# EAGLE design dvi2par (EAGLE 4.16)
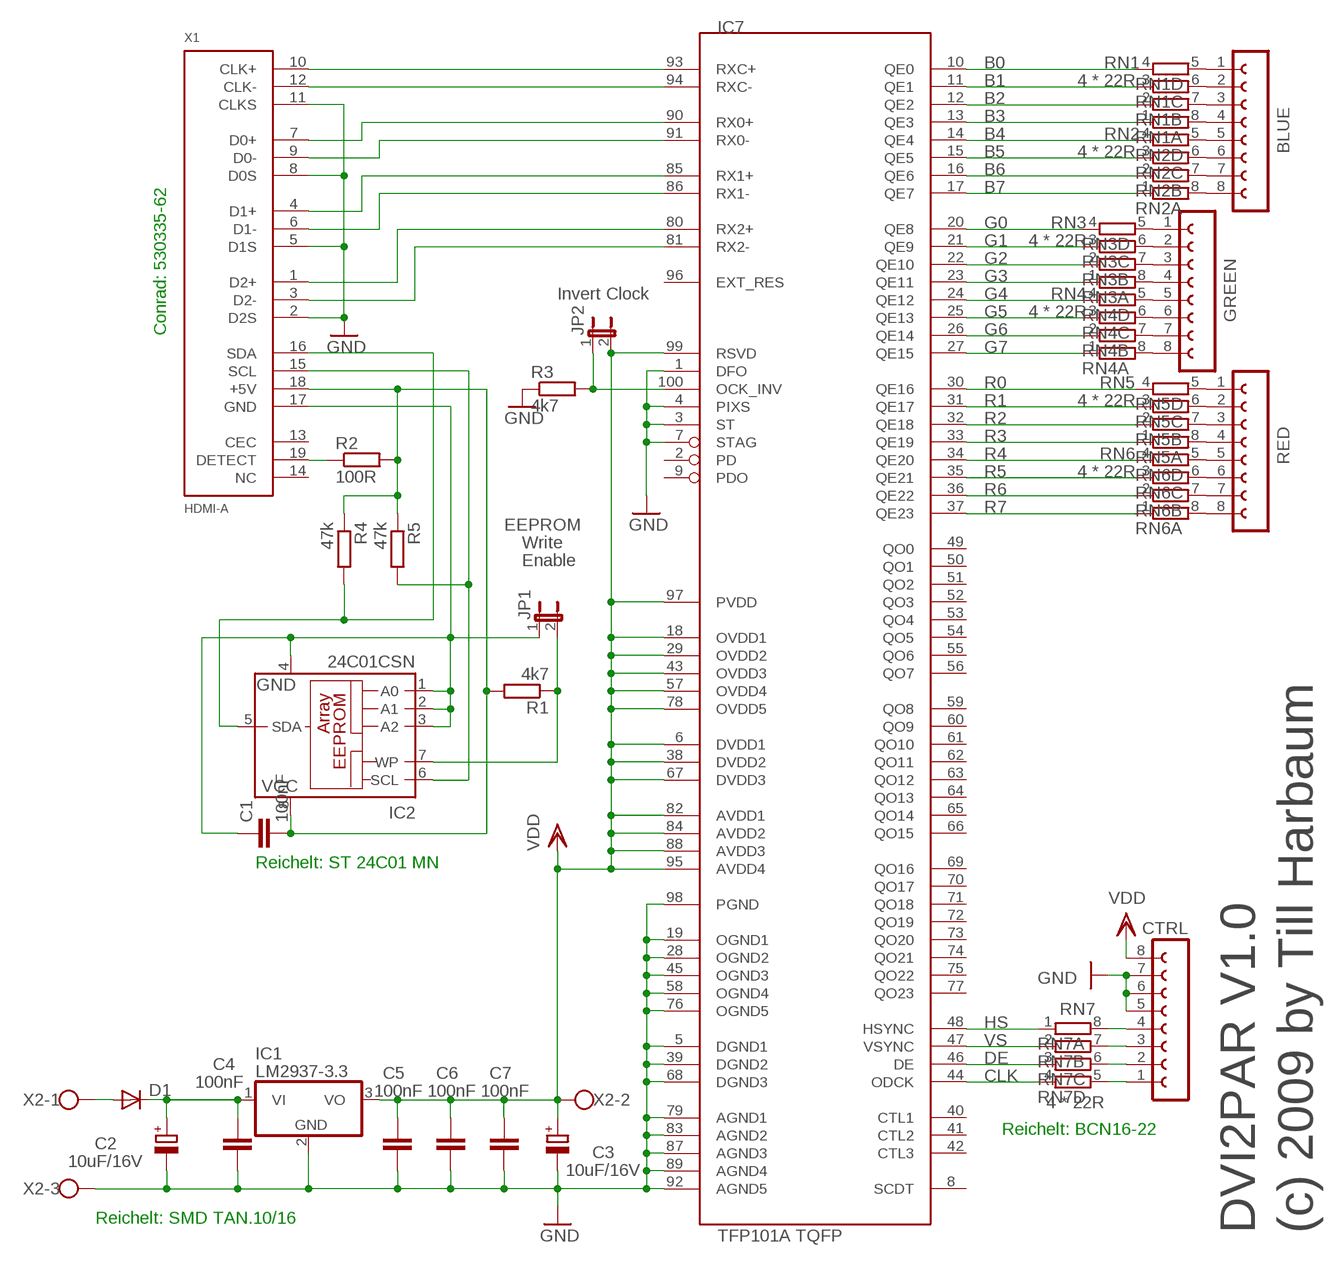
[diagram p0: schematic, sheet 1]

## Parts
BLUE  FE08-1  [FE08]
C1  100nF  C-EUC0805K  [C0805K]
C2  10uF/16V  CPOL-EUCT6032  [CT6032]
C3  10uF/16V  CPOL-EUCT6032  [CT6032]
C4  100nF  C-EUC0805K  [C0805K]
C5  100nF  C-EUC0805K  [C0805K]
C6  100nF  C-EUC0805K  [C0805K]
C7  100nF  C-EUC0805K  [C0805K]
CTRL  FE08-1  [FE08]
D1  DIODE-MELF-MLL41  [MELF-MLL41]
GREEN  FE08-1  [FE08]
IC1  LM2937-3.3  7805T  [TO220H]
IC2  24C01CSN  [SO-08]
IC7  TFP101A TQFP  TFP101ATQFP  [TQ100]
JP1  JP1E  [JP1]
JP2  JP1E  [JP1]
R1  4k7  R-EU_M0805  [M0805]
R2  100R  R-EU_R0805  [R0805]
R3  4k7  R-EU_R0805  [R0805]
R4  47k  R-EU_M0805  [M0805]
R5  47k  R-EU_M0805  [M0805]
RED  FE08-1  [FE08]
RN1  4R-N0603-ARV  [0603-ARV]
RN2  4R-N0603-ARV  [0603-ARV]
RN3  4R-N0603-ARV  [0603-ARV]
RN4  4R-N0603-ARV  [0603-ARV]
RN5  4R-N0603-ARV  [0603-ARV]
RN6  4R-N0603-ARV  [0603-ARV]
RN7  4R-N0603-ARV  [0603-ARV]
X1  HDMI-A  [HDMI-A-PRINT]
X2  W237-03P  [W237-133]

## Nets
B0: IC7.10(QE0) RN1.4
B1: IC7.11(QE1) RN1.3
B2: IC7.12(QE2) RN1.2
B3: IC7.13(QE3) RN1.1
B4: IC7.14(QE4) RN2.4
B5: IC7.15(QE5) RN2.3
B6: IC7.16(QE6) RN2.2
B7: IC7.17(QE7) RN2.1
CLK: IC7.44(ODCK) RN7.4
DDCDATA: IC2.5(SDA) R4.2 X1.16(SDA)
DDCGND: C1.1 IC2.1(A0) IC2.2(A1) IC2.3(A2) IC2.4(GND) JP1.1 X1.17(GND)
DDCVCC: C1.2 IC2.8(VCC) R1.2 R2.2 R4.1 R5.1 X1.18(+5V)
DE: IC7.46(DE) RN7.3
G0: IC7.20(QE8) RN3.4
G1: IC7.21(QE9) RN3.3
G2: IC7.22(QE10) RN3.2
G3: IC7.23(QE11) RN3.1
G4: IC7.24(QE12) RN4.4
G5: IC7.25(QE13) RN4.3
G6: IC7.26(QE14) RN4.2
G7: IC7.27(QE15) RN4.1
GND: C2.- C3.- C4.1 C5.1 C6.1 C7.1 CTRL.5 CTRL.6 CTRL.7 IC1.2(GND) IC7.1(DFO) IC7.3(ST) IC7.4(PIXS) IC7.5(DGND1) IC7.7(STAG) IC7.19(OGND1) IC7.28(OGND2) IC7.39(DGND2) IC7.45(OGND3) IC7.58(OGND4) IC7.68(DGND3) IC7.76(OGND5) IC7.79(AGND1) IC7.83(AGND2) IC7.87(AGND3) IC7.89(AGND4) IC7.92(AGND5) IC7.98(PGND) R3.1 X1.2(D2S) X1.5(D1S) X1.8(D0S) X1.11(CLKS) X2.3
HS: IC7.48(HSYNC) RN7.1
N$2: IC2.7(WP) JP1.2 R1.1
N$3: R2.1 X1.19(DETECT)
N$4: BLUE.4 RN1.8
N$6: BLUE.3 RN1.7
N$8: BLUE.2 RN1.6
N$9: BLUE.1 RN1.5
N$10: BLUE.8 RN2.8
N$11: BLUE.7 RN2.7
N$12: BLUE.6 RN2.6
N$13: BLUE.5 RN2.5
N$14: GREEN.4 RN3.8
N$15: GREEN.3 RN3.7
N$16: GREEN.2 RN3.6
N$17: GREEN.1 RN3.5
N$18: GREEN.8 RN4.8
N$19: GREEN.7 RN4.7
N$20: GREEN.6 RN4.6
N$21: GREEN.5 RN4.5
N$22: RED.4 RN5.8
N$23: RED.3 RN5.7
N$24: RED.2 RN5.6
N$25: RED.1 RN5.5
N$26: RED.8 RN6.8
N$27: RED.7 RN6.7
N$28: RED.6 RN6.6
N$29: RED.5 RN6.5
N$30: CTRL.1 RN7.5
N$31: CTRL.2 RN7.6
N$32: CTRL.3 RN7.7
N$33: CTRL.4 RN7.8
N$34: IC2.6(SCL) R5.2 X1.15(SCL)
N$35: IC7.100(OCK_INV) JP2.1 R3.2
N$36: D1.A X2.1
PWR_IN: C2.+ C4.2 D1.C IC1.1(VI)
R0: IC7.30(QE16) RN5.4
R1: IC7.31(QE17) RN5.3
R2: IC7.32(QE18) RN5.2
R3: IC7.33(QE19) RN5.1
R4: IC7.34(QE20) RN6.4
R5: IC7.35(QE21) RN6.3
R6: IC7.36(QE22) RN6.2
R7: IC7.37(QE23) RN6.1
RX0+: IC7.90(RX0+) X1.7(D0+)
RX0-: IC7.91(RX0-) X1.9(D0-)
RX1+: IC7.85(RX1+) X1.4(D1+)
RX1-: IC7.86(RX1-) X1.6(D1-)
RX2+: IC7.80(RX2+) X1.1(D2+)
RX2-: IC7.81(RX2-) X1.3(D2-)
RXC+: IC7.93(RXC+) X1.10(CLK+)
RXC-: IC7.94(RXC-) X1.12(CLK-)
VDD: C3.+ C5.2 C6.2 C7.2 CTRL.8 IC1.3(VO) IC7.6(DVDD1) IC7.18(OVDD1) IC7.29(OVDD2) IC7.38(DVDD2) IC7.43(OVDD3) IC7.57(OVDD4) IC7.67(DVDD3) IC7.78(OVDD5) IC7.82(AVDD1) IC7.84(AVDD2) IC7.88(AVDD3) IC7.95(AVDD4) IC7.97(PVDD) IC7.99(RSVD) JP2.2 X2.2
VS: IC7.47(VSYNC) RN7.2
Unconnected: IC7.2(PD) IC7.8(SCDT) IC7.9(PDO) IC7.40(CTL1) IC7.41(CTL2) IC7.42(CTL3) IC7.49(QO0) IC7.50(QO1) IC7.51(QO2) IC7.52(QO3) IC7.53(QO4) IC7.54(QO5) IC7.55(QO6) IC7.56(QO7) IC7.59(QO8) IC7.60(QO9) IC7.61(QO10) IC7.62(QO11) IC7.63(QO12) IC7.64(QO13) IC7.65(QO14) IC7.66(QO15) IC7.69(QO16) IC7.70(QO17) IC7.71(QO18) IC7.72(QO19) IC7.73(QO20) IC7.74(QO21) IC7.75(QO22) IC7.77(QO23) IC7.96(EXT_RES) X1.13(CEC) X1.14(NC)

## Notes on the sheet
- RN1
- 4 * 22R
- RN2
- 4 * 22R
- RN3
- 4 * 22R
- Invert Clock | RN4
- 4 * 22R
- Conrad: 530335-62
- RN5
- 4 * 22R
- RN6
- 4 * 22R
- EEPROM
- Write
- Enable
- Reichelt: ST 24C01 MN
- RN7
- 4 * 22R
- Reichelt: BCN16-22
- Reichelt: SMD TAN.10/16
- DVI2PAR V1.0 | (c) 2009 by Till Harbaum

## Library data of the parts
BLUE CTRL GREEN RED = con-lsta:FE08-1: FEMALE HEADER
C1 C4-C7 = rcl:C-EU: CAPACITOR, European symbol
C2 C3 = rcl:CPOL-EU: POLARIZED CAPACITOR, European symbol
D1 = diode:DIODE-: DIODE
IC1 = linear:78*: Positive VOLTAGE REGULATOR Source: http://cache.national.com/ds/LM/LM78L05.pdf http://www.fairchildsemi.com/ds/LM/LM7805.pdf
IC2 = microchip:24C*: Serial EEPROM 1 K/2 K/4 K
IC7 = DVI:TFP101A
JP1 JP2 = jumper:JP1E: JUMPER
R1-R5 = rcl:R-EU_: RESISTOR, European symbol
RN1-RN7 = resistor-dil:4R-N: Array Chip Resistor Source: RS Component / Phycomp
X1 = hdmi:HDMI-A
X2 = con-wago-508:W237-03P: WAGO SREW CLAMP

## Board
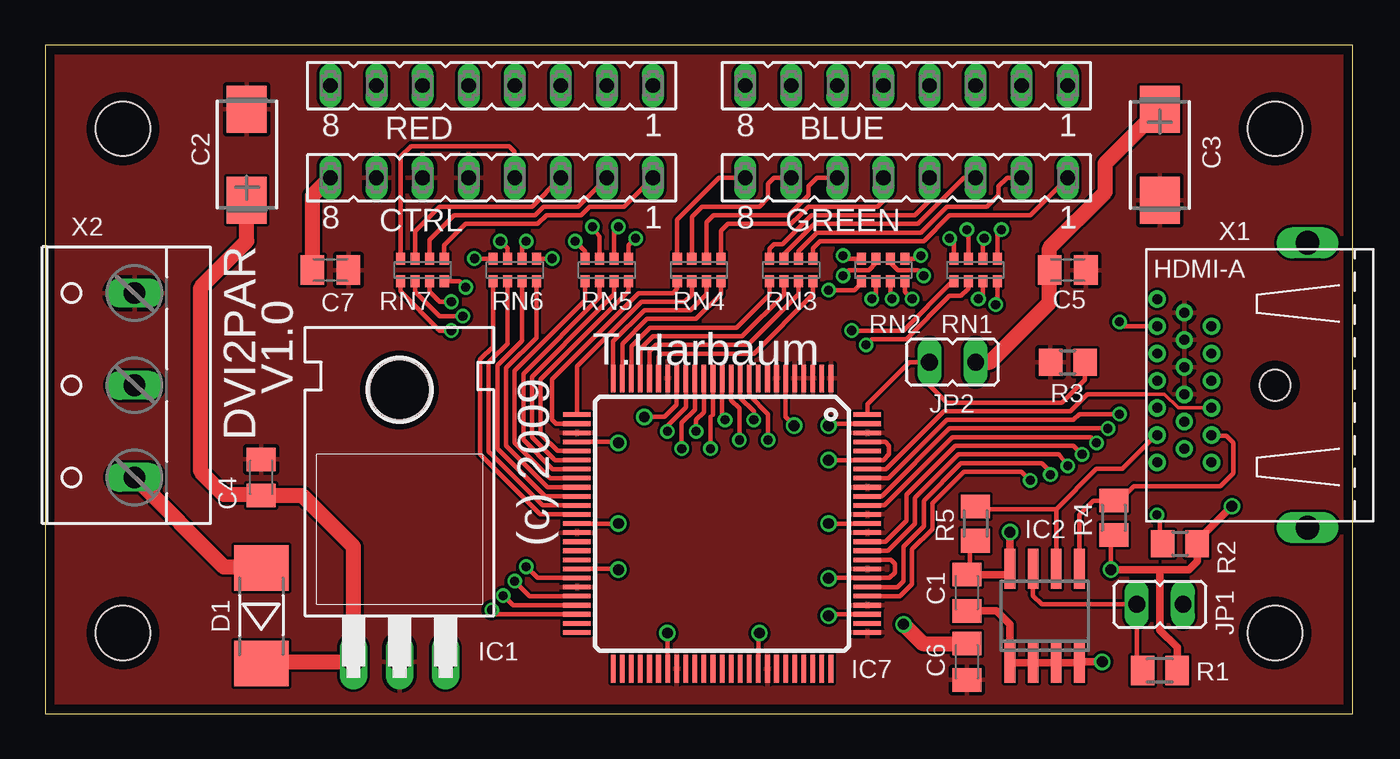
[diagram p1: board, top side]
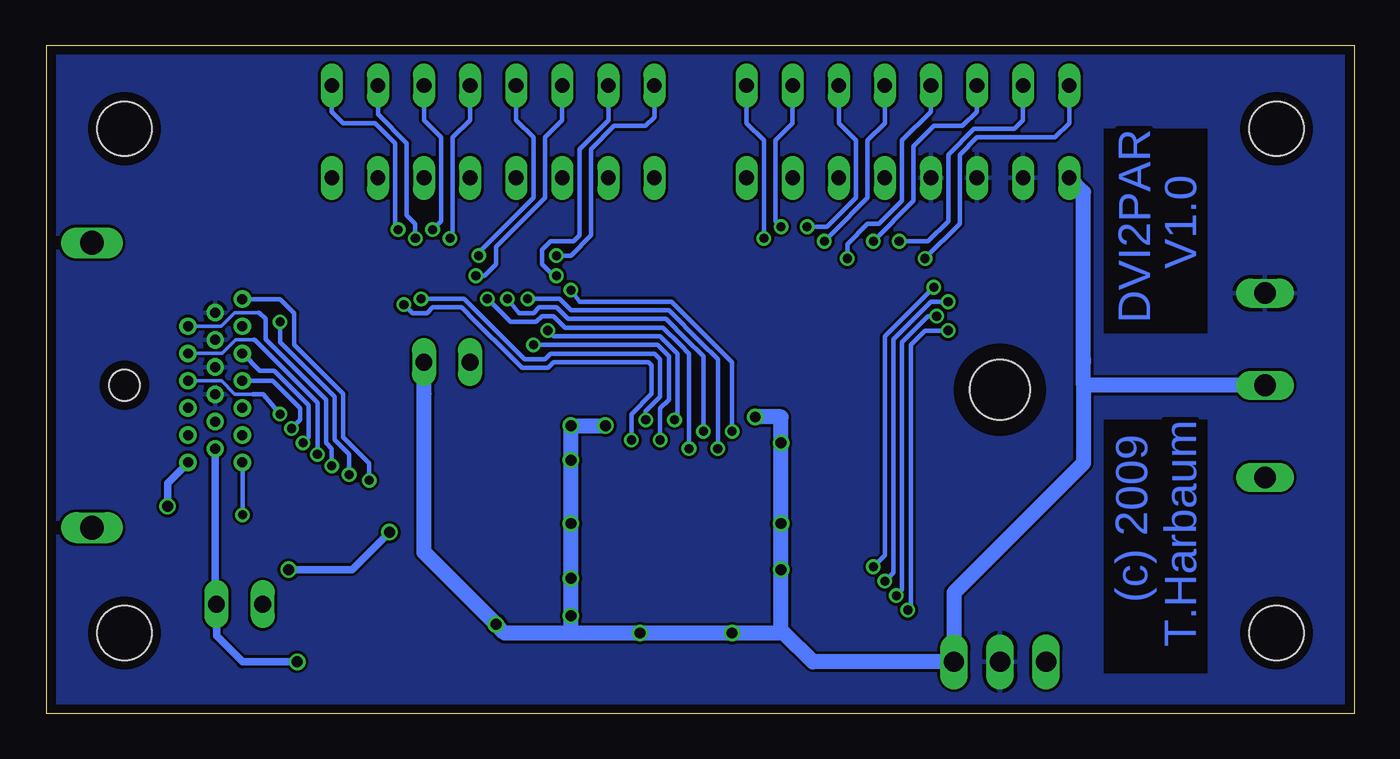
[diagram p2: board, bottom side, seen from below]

Size 72.06 x 36.82 mm. Coordinates in mm from the lower left corner, seen from the top.
Outline: 0,0 72.06,0 72.06,36.82 0,36.82 0,0
Copper layers (1*16): Top 0.035mm / dielectric 1.5mm / Bottom 0.035mm
Design rules "PCB-POOL": minimum track width 6mil, minimum drill 12mil, track to track 6mil, track to pad 6mil, pad to pad 6mil, via to via 6mil, smd to smd 6mil, copper to edge 20mil, drill to drill 8mil, minimum pad ring 8mil, minimum via ring 6mil, stop-mask expansion 3mil, vias tented up to drill 0mil, thermal gap 8mil
Holes 3 mm at 4.28,4.44 67.78,4.44 67.78,32.22 4.28,32.22
bRestrict: area 8.1,2.2 to 13.8,16.2; area 8.1,20.9 to 13.8,32.2

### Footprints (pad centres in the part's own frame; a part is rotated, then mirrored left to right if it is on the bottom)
FE08 = drill 0.813 long: 1 -8.89,0; 2 -6.35,0; 3 -3.81,0; 4 -1.27,0; 5 1.27,0; 6 3.81,0; 7 6.35,0; 8 8.89,0
C0805K = smd 1.3 x 1.6: 1 -1,0; 2 1,0
CT6032 = smd 2.6 x 2.2: + 2.5,0; - -2.5,0
MELF-MLL41 = smd 2.5 x 3: A 2.625,0; C -2.625,0
TO220H = drill 1.118 long: 1 -2.54,-10.16; 2 0,-10.16; 3 2.54,-10.16 | hole 3.302: 0,4.826
SO-08 = smd 0.6 x 2.2: 1 -1.905,-2.6; 2 -0.635,-2.6; 3 0.635,-2.6; 4 1.905,-2.6; 5 1.905,2.6; 6 0.635,2.6; 7 -0.635,2.6; 8 -1.905,2.6
TQ100 = smd 1.524 x 0.254: 1 -8,6; 2 -8,5.5; 3 -8,5; 4 -8,4.5; 5 -8,4; 6 -8,3.5; 7 -8,3; 8 -8,2.5; 9 -8,2; 10 -8,1.5; 11 -8,1; 12 -8,0.5; 13 -8,0; 14 -8,-0.5; 15 -8,-1; 16 -8,-1.5; 17 -8,-2; 18 -8,-2.5; 19 -8,-3; 20 -8,-3.5; 21 -8,-4; 22 -8,-4.5; 23 -8,-5; 24 -8,-5.5; 25 -8,-6; 51 8,-6; 52 8,-5.5; 53 8,-5; 54 8,-4.5; 55 8,-4; 56 8,-3.5; 57 8,-3; 58 8,-2.5; 59 8,-2; 60 8,-1.5; 61 8,-1; 62 8,-0.5; 63 8,0; 64 8,0.5; 65 8,1; 66 8,1.5; 67 8,2; 68 8,2.5; 69 8,3; 70 8,3.5; 71 8,4; 72 8,4.5; 73 8,5; 74 8,5.5; 75 8,6 | smd 0.254 x 1.524: 26 -6,-8; 27 -5.5,-8; 28 -5,-8; 29 -4.5,-8; 30 -4,-8; 31 -3.5,-8; 32 -3,-8; 33 -2.5,-8; 34 -2,-8; 35 -1.5,-8; 36 -1,-8; 37 -0.5,-8; 38 0,-8; 39 0.5,-8; 40 1,-8; 41 1.5,-8; 42 2,-8; 43 2.5,-8; 44 3,-8; 45 3.5,-8; 46 4,-8; 47 4.5,-8; 48 5,-8; 49 5.5,-8; 50 6,-8; 76 6,8; 77 5.5,8; 78 5,8; 79 4.5,8; 80 4,8; 81 3.5,8; 82 3,8; 83 2.5,8; 84 2,8; 85 1.5,8; 86 1,8; 87 0.5,8; 88 0,8; 89 -0.5,8; 90 -1,8; 91 -1.5,8; 92 -2,8; 93 -2.5,8; 94 -3,8; 95 -3.5,8; 96 -4,8; 97 -4.5,8; 98 -5,8; 99 -5.5,8; 100 -6,8
JP1 = drill 0.914 long: 1 0,-1.27; 2 0,1.27
M0805 = smd 1.3 x 1.6: 1 -0.95,0; 2 0.95,0
R0805 = smd 1.3 x 1.5: 1 -0.95,0; 2 0.95,0
0603-ARV = smd 0.5 x 0.65: 1 -1.2,-0.625; 2 -0.4,-0.625; 3 0.4,-0.625; 4 1.2,-0.625; 5 1.2,0.625; 6 0.4,0.625; 7 -0.4,0.625; 8 -1.2,0.625
HDMI-A-PRINT = drill 0.55 round: 1 4.75,6.5; 2 4,5; 3 3.25,6.5; 4 3.25,3.5; 5 2.5,5; 6 1.75,3.5; 7 1.75,6.5; 8 1,5; 9 0.25,6.5; 10 0.25,3.5; 11 -0.5,5; 12 -1.25,3.5; 13 -1.25,6.5; 14 -2,5; 15 -2.75,6.5; 16 -2.75,3.5; 17 -3.5,5; 18 -4.25,3.5; 19 -4.25,6.5 | drill 1.3 long: P$1 -7.85,-1.8; P$2 7.85,-1.8 | hole 1.7: 0,0
W237-133 = drill 1.194 long: 1 -5.08,-0.635; 2 0,-0.635; 3 5.08,-0.635

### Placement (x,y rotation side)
BLUE  47.46,34.6 180 top
C1  50.79,6.66 90 top
C2  11.11,30.79 270 top
C3  61.43,30.79 90 top
C4  11.9,13.01 270 top
C5  56.35,24.44 180 top
C6  50.79,2.85 90 top
C7  15.71,24.44 180 top
CTRL  24.6,29.52 180 top
D1  11.9,5.39 90 top
GREEN  47.46,29.52 180 top
IC1  19.52,13.01 0 top
IC2  55.08,5.39 0 top
IC7  37.3,10.47 270 top
JP1  61.43,6.03 90 top
JP2  50,19.36 270 top
R1  61.43,2.38 0 top
R2  62.54,9.36 0 top
R3  56.35,19.36 0 top
R4  58.89,10.79 90 top
R5  51.27,10.47 90 top
RED  24.6,34.6 180 top
RN1  51.27,24.44 0 top
RN2  46.19,24.44 0 top
RN3  41.11,24.44 0 top
RN4  36.03,24.44 0 top
RN5  30.95,24.44 0 top
RN6  25.87,24.44 0 top
RN7  20.79,24.44 0 top
X1  67.78,18.09 90 top
X2  4.28,18.09 90 top

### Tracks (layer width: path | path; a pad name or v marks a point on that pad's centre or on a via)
B0  (via drill 0.5)
  Top 0.254: IC7.10 38.8,17.54 39.84,16.5 v39.84,15.08 | v52.38,22.54 | RN1.4 52.47,22.63 v52.38,22.54
  Bottom 0.254: v39.84,15.08 39.84,16.5 38.73,17.62 38.73,19.2 38.89,19.36 44.13,19.36 44.44,19.04 45.87,19.04 46.51,19.68 48.41,21.58 49.21,22.38 50.79,22.38 51.11,22.06 51.9,22.06 v52.38,22.54
B1  (via drill 0.5)
  Top 0.254: IC7.11 38.3,17.41 39.05,16.66 v39.05,16.19 | v51.43,22.85 | RN1.3 51.67,23.1 v51.43,22.85
  Bottom 0.254: v39.05,16.19 39.05,16.66 38.25,17.46 38.25,19.52 38.57,19.84 44.28,19.84 44.6,19.52 45.71,19.52 49.05,22.85 v51.43,22.85
B2  (via drill 0.5)
  Top 0.254: IC7.12 37.8,17.27 38.25,16.82 v38.25,15.08 | v45.24,20.31 45.55,20.63 47.46,20.63 49.84,23.01 50.48,23.01 50.87,23.41 RN1.2
  Bottom 0.254: v38.25,15.08 38.25,16.82 37.78,17.3 37.78,19.68 38.41,20.31 v45.24,20.31
B3  (via drill 0.5)
  Top 0.254: IC7.13 37.3,16.35 v37.46,16.19 | RN1.1 50.01,23.82 47.3,21.11 v44.44,21.11
  Bottom 0.254: v37.46,16.19 37.3,16.35 37.3,19.84 38.25,20.79 43.97,20.79 44.13,20.79 v44.44,21.11
B4  (via drill 0.5)
  Top 0.254: IC7.14 36.8,16.48 36.66,16.35 v36.66,14.6 36.66,15.08 | v47.78,22.85 | RN2.4 47.39,23.24 v47.78,22.85
  Bottom 0.254: v36.66,14.6 36.66,19.84 37.14,20.31 | 37.14,20.31 | 37.14,20.31 38.09,21.27 43.49,21.27 44.13,21.9 44.76,21.9 45.08,21.58 46.19,21.58 46.51,21.58 v47.78,22.85 | v47.78,22.85
B5  (via drill 0.5)
  Top 0.254: RN2.3 46.59,22.94 v46.67,22.85 | v35.87,15.55 35.87,16.19 36.3,16.62 IC7.15
  Bottom 0.254: v35.87,15.55 35.87,19.68 36.82,20.63 37.93,21.74 43.33,21.74 43.97,22.38 44.92,22.38 45.24,22.06 45.55,22.06 46.03,22.06 v46.67,22.85
B6  (via drill 0.5)
  Top 0.254: RN2.2 45.79,23.09 v45.55,22.85 | IC7.16 35.8,16.75 35.08,16.03 35.08,15.08 v35.08,14.6
  Bottom 0.254: v35.08,14.6 35.08,19.52 36.03,20.47 | 36.03,20.47 | 36.03,20.47 37.78,22.22 43.17,22.22 43.81,22.85 v45.55,22.85
B7  (via drill 0.5)
  Top 0.254: RN2.1 44.99,23.88 44.99,23.72 44.6,23.33 v43.17,23.33 | IC7.17 35.3,16.89 34.28,15.87 v34.28,15.55
  Bottom 0.254: v34.28,15.55 34.28,19.36 37.62,22.7 42.7,22.7 v43.17,23.33
CLK  (via drill 0.5)
  Top 0.254: RN7.4 22.84,23.82 v23.17,23.49 | IC7.44 27.12,7.47 v26.5,8.09
  Bottom 0.254: v23.17,23.49 25.87,20.79 25.87,8.73 v26.5,8.09
DDCDATA
  Top 0.254: 64.76,12.54 65.48,13.25 65.48,14.92 65.08,15.31 64.29,15.31 64.28,15.32 X1.16 | IC2.5 56.98,10.95 57.78,11.74 59.05,11.74 | 59.05,11.74 R4.2 | 59.05,11.74 59.2,11.74 60,12.54 64.76,12.54 | 64.76,12.54
DDCGND  (via drill 0.6)
  Top 0.406: C1.1 52.43,5.66 53.17,4.92 IC2.1 54.38,2.79 54.44,2.85 IC2.2 55.65,2.79 55.71,2.85 IC2.3 56.92,2.79 56.98,2.85 | 56.98,2.85 IC2.4 | 56.98,2.85 v58.25,2.85
  Bottom 0.406: v58.25,2.85 61.27,2.85 62.7,4.28 JP1.1 | JP1.1 | X1.17 62.78,6.11 JP1.1
DDCVCC  (via drill 0.6)
  Top 0.254: 58.89,9.68 R4.1 | 58.89,9.68 | 58.89,9.68 58.73,9.52 v58.73,7.93 | C1.2 50.79,7.61 | C1.2 | C1.2 50.95,7.82 50.95,9.36 R5.1
  Top 0.406: C1.2 53.13,7.66 53.17,8.09 | 53.17,8.09 IC2.8 | v53.17,10 53.17,8.25 53.17,8.09 | R1.2 62.38,3.65 61.43,4.6 61.43,7.93 | v58.73,7.93 | v58.73,7.93 61.43,7.93 | 61.43,7.93 63.02,7.93 63.49,8.41 R2.2 63.5,9.52 v65.4,11.42
  Bottom 0.406: v58.73,7.93 55.24,7.93 v53.17,10 | X1.18 64.28,13.81 64.29,13.81 65.4,12.69 v65.4,11.42
DE  (via drill 0.5)
  Top 0.254: RN7.3 21.19,23.25 21.74,22.7 v22.38,22.7 22.54,22.7 | IC7.46 26.69,6.47 v25.87,7.3
  Bottom 0.254: v22.38,22.7 23.33,22.7 25.39,20.63 25.39,7.77 v25.87,7.3
G0
  Top 0.254: IC7.20 33.8,19.67 33.97,19.84 39.05,19.84 42.31,23.1 RN3.4
G1
  Top 0.254: IC7.21 33.3,19.97 33.65,20.31 38.73,20.31 41.51,23.1 RN3.3
G2
  Top 0.254: IC7.22 32.8,20.1 33.49,20.79 38.41,20.79 40.71,23.09 RN3.2
G3
  Top 0.254: IC7.23 32.3,20.24 33.33,21.27 38.09,21.27 39.91,23.08 RN3.1
G4
  Top 0.254: IC7.24 31.8,20.37 33.17,21.74 35.87,21.74 37.23,23.1 RN4.4
G5
  Top 0.254: IC7.25 31.3,20.51 33.01,22.22 35.55,22.22 36.43,23.1 RN4.3
G6
  Top 0.254: IC7.26 29.3,19.14 32.85,22.7 35.24,22.7 35.63,23.09 RN4.2
G7
  Top 0.254: IC7.27 28.15,15.97 27.93,16.19 27.93,18.41 32.7,23.17 34.6,23.17 34.83,23.4 RN4.1
GND
  pour Top: -0.01,-0.01 -0.01,36.82 72.07,36.82 72.07,-0.01
  pour Bottom: -0.01,-0.01 -0.01,36.83 72.07,36.83 72.07,-0.01 71.91,-0.01
HS  (via drill 0.5)
  Top 0.254: RN7.1 19.59,23.26 21.74,21.11 v22.38,21.11 | v24.6,5.71 24.76,5.55 | 24.76,5.55 v24.6,5.71 | v24.6,5.71 | IC7.48 24.84,5.47 24.76,5.55
  Bottom 0.254: v22.38,21.11 23.65,21.11 24.44,20.31 24.44,5.87 v24.6,5.71
N$2
  Top 0.254: IC2.7 54.44,6.5 54.92,6.03 JP1.2 | JP1.2 | R1.1 60.16,2.69 JP1.2
N$3  (via drill 0.5)
  Top 0.254: v61.27,10.95 61.43,10.79 61.43,10 61.27,9.36 R2.1
  Bottom 0.254: X1.19 61.28,13.81 61.27,13.81 v61.27,10.95
N$4  (via drill 0.5)
  Top 0.254: RN1.8 50.07,25.94 v49.84,26.19
  Bottom 0.254: v49.84,26.19 49.68,26.35 49.68,31.74 48.73,32.7 BLUE.4
N$6  (via drill 0.5)
  Top 0.254: RN1.7 50.87,26.59 v50.79,26.66
  Bottom 0.254: BLUE.3 51.27,32.7 50.32,31.74 50.32,27.14 v50.79,26.66
N$8  (via drill 0.5)
  Top 0.254: RN1.6 51.67,26.11 v51.75,26.19
  Bottom 0.254: v51.75,26.19 51.75,26.98 52.22,27.46 52.22,31.43 53.81,33.01 BLUE.2
N$9  (via drill 0.5)
  Top 0.254: RN1.5 52.47,26.44 v52.7,26.66
  Bottom 0.254: v52.7,26.66 | v52.7,26.66 52.86,26.82 52.86,31.43 53.97,32.54 55.71,32.54 56.35,33.17 BLUE.1
N$10  (via drill 0.5)
  Top 0.254: RN2.8 44.14,25.07 v43.97,25.24
  Bottom 0.254: v43.97,25.24 43.17,25.24 42.06,26.35 42.06,31.11 40.79,32.38 39.05,32.38 38.57,32.86 BLUE.8
N$11  (via drill 0.5)
  Top 0.254: RN2.7 45.79,24.84 45.4,24.44 44.28,24.44 v43.97,24.12
  Bottom 0.254: v43.97,24.12 44.13,24.12 44.76,24.76 44.76,25.55 44.28,26.03 43.01,26.03 42.7,26.35 42.7,31.11 41.11,32.7 BLUE.7
N$12  (via drill 0.5)
  Top 0.254: RN2.6 46.59,24.84 46.98,24.44 48.09,24.44 v48.41,24.12
  Bottom 0.254: v48.41,24.12 47.94,24.12 47.3,24.76 47.3,25.71 44.6,28.41 44.6,31.74 43.65,32.7 BLUE.6
N$13  (via drill 0.5)
  Top 0.254: RN2.5 48.08,25.07 v48.25,25.24
  Bottom 0.254: v48.25,25.24 48.25,25.39 46.35,27.3 | 46.35,27.3 | 46.35,27.3 45.24,28.41 45.24,31.74 46.19,32.7 BLUE.5
N$14
  Top 0.254: GREEN.4 48.73,28.25 47.94,27.46 42.22,27.46 40.63,25.87 40.16,25.87 39.91,25.62 RN3.8
N$15
  Top 0.254: 48.09,26.98 42.38,26.98 40.71,25.31 RN3.7 | GREEN.3 50.63,29.52 48.09,26.98 | 48.09,26.98
N$16
  Top 0.254: 51.9,27.93 49.68,27.93 48.25,26.51 42.54,26.51 41.51,25.48 RN3.6 | 51.9,27.93 | GREEN.2 53.02,29.52 52.54,29.05 52.54,28.57 51.9,27.93
N$17
  Top 0.254: GREEN.1 54.29,27.46 49.84,27.46 48.41,26.03 42.7,26.03 42.31,25.64 RN3.5
N$18
  Top 0.254: RN4.8 34.83,27.21 37.14,29.52 GREEN.8
N$19
  Top 0.254: RN4.7 35.63,27.38 36.19,27.93 39.36,27.93 39.84,28.41 39.84,29.2 40.16,29.52 GREEN.7
N$20
  Top 0.254: RN4.6 36.43,27.06 36.82,27.46 40.95,27.46 42.06,28.57 42.06,29.05 42.54,29.52 GREEN.6
N$21
  Top 0.254: RN4.5 37.23,26.59 37.62,26.98 41.11,26.98 41.59,27.46 42.06,27.93 45.87,27.93 46.19,28.25 GREEN.5
N$22  (via drill 0.5)
  Top 0.254: RN5.8 29.75,25.48 v29.2,26.03
  Bottom 0.254: v29.2,26.03 | v29.2,26.03 28.73,26.51 26.82,28.41 26.82,31.59 25.87,32.54 RED.4
N$23  (via drill 0.5)
  Top 0.254: RN5.7 30.55,26.27 v30.16,26.82
  Bottom 0.254: v30.16,26.82 29.04,26.82 27.46,28.41 27.46,31.59 28.41,32.54 RED.3
N$24  (via drill 0.5)
  Top 0.254: RN5.6 31.35,26.58 v31.58,26.82
  Bottom 0.254: v31.58,26.82 31.9,27.14 31.9,31.59 30.95,32.54 RED.2
N$25  (via drill 0.5)
  Top 0.254: RN5.5 32.15,25.8 v32.54,26.19
  Bottom 0.254: v32.54,26.19 32.54,31.59 33.49,32.54 RED.1
N$26  (via drill 0.5)
  Top 0.254: RN6.8 23.66,25.07 v23.65,25.08
  Bottom 0.254: v23.65,25.08 21.74,26.98 21.74,30.79 20.79,31.74 16.5,31.74 15.71,32.54 RED.8
N$27  (via drill 0.5)
  Top 0.254: RN6.7 25.47,25.64 v25.08,26.03
  Bottom 0.254: v25.08,26.03 23.49,26.03 22.38,27.14 22.38,30.79 20.95,32.22 18.73,32.22 18.25,32.7 RED.7
N$28  (via drill 0.5)
  Top 0.254: RN6.6 26.27,25.79 v26.5,26.03
  Bottom 0.254: v26.5,26.03 | v26.5,26.03 24.28,28.25 24.28,31.27 23.17,32.38 21.58,32.38 20.79,33.17 RED.6
N$29  (via drill 0.5)
  Top 0.254: RN6.5 v27.92,25.07 v27.93,25.08
  Bottom 0.254: v27.93,25.08 27.93,25.87 26.82,26.98 26.19,26.98 24.92,28.25 24.92,31.59 23.33,33.17 RED.5
N$30
  Top 0.254: RN7.5 21.99,25.8 23.17,26.98 27.14,26.98 27.62,27.46 29.52,27.46 30,27.93 31.9,27.93 CTRL.1
N$31
  Top 0.254: RN7.6 21.19,26.11 22.54,27.46 26.98,27.46 27.46,27.93 29.36,27.93 CTRL.2
N$32
  Top 0.254: RN7.7 20.39,26.58 21.74,27.93 26.82,27.93 CTRL.3
N$33
  Top 0.254: RN7.8 19.59,30.7 20.15,31.27 25.55,31.27 25.87,30.95 CTRL.4
N$34
  Top 0.254: X1.15 61.28,15.38 61.27,15.39 59.37,13.49 57.94,13.49 55.71,11.27 | 55.71,9.2 IC2.6 | 55.71,9.2 | 55.71,11.27 55.71,9.2 | R5.2 50.95,11.27 55.71,11.27
N$35
  Top 0.254: IC7.100 45.3,17.04 47.62,19.36 JP2.1 48.73,18.09 49.68,17.14 56.03,17.14 57.3,18.41 R3.2
N$36
  Top 0.813: D1.A 11.83,8.09 9.84,8.09 X2.1
PWR_IN
  Top 0.813: D1.C 11.98,2.85 IC1.1 16.98,9.2 14.17,12.01 C4.2 11.85,12.06 9.84,12.06 8.57,13.33 8.57,23.49 11.11,26.03 C2.+
R0
  Top 0.254: RN5.4 32.15,23.26 27.3,18.41 27.3,15.39 28.22,14.47 IC7.30
R1
  Top 0.254: RN5.3 31.35,23.1 30.47,22.22 | 30.47,22.22 | 30.47,22.22 26.82,18.57 26.82,15.23 28.08,13.97 IC7.31
R2
  Top 0.254: RN5.2 30.55,22.93 26.35,18.73 26.35,15.08 27.95,13.47 IC7.32
R3
  Top 0.254: RN5.1 29.75,22.77 25.87,18.89 25.87,14.92 27.81,12.97 IC7.33
R4
  Top 0.254: RN6.4 27.07,20.72 25.39,19.04 25.39,14.76 27.68,12.47 IC7.34
R5
  Top 0.254: RN6.3 26.27,20.56 24.92,19.2 24.92,14.6 27.54,11.97 IC7.35
R6
  Top 0.254: RN6.2 25.47,20.39 24.6,19.52 | 24.6,19.52 | 24.6,19.52 24.44,19.36 24.44,14.44 24.6,14.28 27.41,11.47 IC7.36
R7
  Top 0.254: RN6.1 24.67,20.23 23.96,19.52 23.96,14.28 27.27,10.97 IC7.37
RX0+  (via drill 0.5)
  Top 0.254: IC7.90 46.24,11.47 50,15.23 57.62,15.23 v57.94,14.92
  Bottom 0.254: v57.94,14.92 57.62,15.23 57.62,15.55 57.62,16.98 59.52,18.89 60.32,18.89 X1.7
RX0-  (via drill 0.5)
  Top 0.254: IC7.91 46.1,11.97 49.84,15.71 v58.57,15.71
  Bottom 0.254: v58.57,15.71 58.1,16.19 58.1,16.82 59.62,18.34 X1.9
RX1+  (via drill 0.5)
  Top 0.254: IC7.85 46.44,8.97 47.94,10.47 47.94,11.9 50.32,14.28 55.87,14.28 v56.35,13.65
  Bottom 0.203: X1.4 62.45,21.34 61.7,22.09 60.4,22.09
  Bottom 0.254: 60.4,22.09 60.34,22.09 60,21.74 60,20.63 56.67,17.3 56.67,14.92 56.35,14.6 56.35,14.12 v56.35,13.65
RX1-  (via drill 0.5)
  Top 0.254: IC7.86 46.3,9.47 47.46,10.63 47.46,12.06 50.16,14.76 56.67,14.76 v57.14,14.28
  Bottom 0.203: X1.6 62.4,19.84 61.65,20.59 60.66,20.59
  Bottom 0.254: v57.14,14.28 57.14,17.14 60.59,20.59 60.66,20.59
RX2+  (via drill 0.5)
  Top 0.254: IC7.80 47.11,6.47 47.78,7.14 47.78,9.04 48.89,10.15 48.89,11.58 50.63,13.33 53.81,13.33 v54.29,12.85
  Bottom 0.254: X1.1 59.19,22.84 58.41,22.06 58.41,20.31 55.71,17.62 55.71,15.23 54.29,13.81 v54.29,12.85
RX2-  (via drill 0.5)
  Top 0.254: IC7.81 46.98,6.97 47.3,7.3 47.3,9.2 48.25,10.15 | 48.25,10.15 | 48.25,10.15 48.41,10.31 48.41,11.74 50.48,13.81 54.92,13.81 55.4,13.33 v55.4,13.17 | X1.3 59.45,21.34 v59.21,21.58
  Bottom 0.254: v59.21,21.58 59.21,20.47 56.19,17.46 56.19,15.08 55.4,14.28 v55.4,13.17
RXC+  (via drill 0.5)
  Top 0.254: IC7.93 46.47,12.97 49.68,16.19 56.67,16.19 56.98,16.5 v59.21,16.5
  Bottom 0.203: X1.10 62.43,18.34 61.7,17.59 60.7,17.59
  Bottom 0.254: 60.7,17.59 60.13,17.59 v59.21,16.5
RXC-
  Top 0.203: X1.12 62.45,16.84 61.68,17.59 60.7,17.59
  Top 0.254: IC7.94 46.33,13.47 49.52,16.66 56.51,16.66 57.43,17.59 60.7,17.59
VDD  (via drill 0.6)
  Top 0.254: IC7.43 31.54,7.97 v31.58,7.93 | v31.58,10.47 IC7.38 | IC7.29 31.53,14.97 v31.58,14.92 | IC7.18 34.8,17.02 34.12,16.35 v33.01,16.35 | IC7.57 34.3,4.42 v34.28,4.44 | IC7.67 39.3,4.38 v39.36,4.44 | IC7.78 43.25,5.47 v43.17,5.39 | v43.17,7.46 43.19,7.47 IC7.82 46.52,7.47 46.82,7.77 46.82,8.25 46.6,8.47 IC7.84 | v43.17,10.47 IC7.88 | IC7.97 46.29,14.97 46.51,14.76 46.51,14.28 46.19,13.96 45.4,13.96 45.39,13.97 IC7.95 v43.18,13.97 v43.17,13.96 | IC7.99 43.28,15.97 v43.17,15.87 | IC7.6 40.8,16.35 v41.27,15.87
  Top 0.813: C6.2 48.36,3.85 v47.3,4.92 | JP2.2 52.06,19.36 55.35,22.65 C5.2 55.35,25.66 58.41,28.73 58.41,30.32 61.43,33.33 C3.+ | C7.2 14.71,28.52 CTRL.8
  Bottom 0.254: 50.95,17.62 51.27,17.93 JP2.2
  Bottom 0.813: X2.2 14.92,18.09 | 14.92,18.09 14.92,19.36 | 14.92,19.36 14.92,19.52 | CTRL.8 14.92,28.73 14.92,19.36 | 14.92,18.09 14.92,13.81 19.52,9.2 22.06,6.66 IC1.3 29.84,2.85 31.43,4.44 31.58,4.44 | 31.58,4.44 v31.58,7.93 v31.58,10.47 v31.58,14.92 31.58,16.35 v33.01,16.35 | 31.58,4.44 v34.28,4.44 v39.36,4.44 43.17,4.44 | 43.17,4.44 46.82,4.44 v47.3,4.92 51.27,8.88 51.27,19.04 JP2.2 | 43.17,4.44 | 43.17,4.44 v43.17,5.39 v43.17,7.46 v43.17,10.47 v43.17,13.96 v43.17,15.87 v41.27,15.87
VS  (via drill 0.5)
  Top 0.254: RN7.2 20.39,23.25 21.74,21.9 v23.01,21.9 | IC7.47 25.77,5.97 v25.23,6.5
  Bottom 0.254: v23.01,21.9 23.49,21.9 24.92,20.47 24.92,6.82 v25.23,6.5

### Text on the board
Bottom: DVI2PAR | V1.0 | T.Harbaum | (c) 2009
tNames: T.Harbaum | V1.0 | DVI2PAR | (c) 2009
